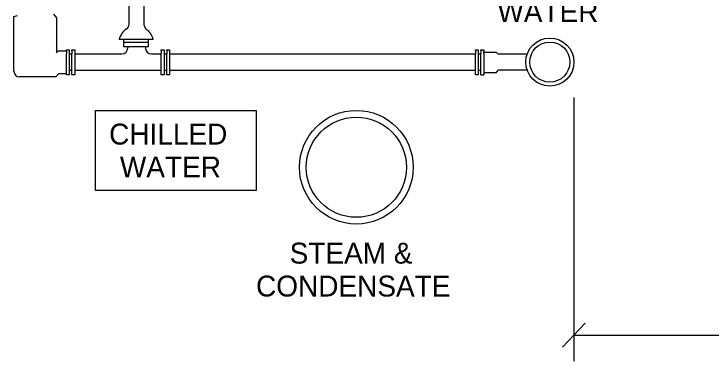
# Model space of a CAD drawing. Extents: x 27101070.6 to 27101150.6, y 1158854.7 to 1158902.9.
# Drawn here: x 27101080.64 to 27101098.02, y 1158875.06 to 1158883.73 of the extents above; entities that cross this region are included whole.
import ezdxf

# ---------------------------------------------------------------- set-up
doc = ezdxf.new("R2010")
doc.units = 0
for name, color, linetype in [('Default', 7, 'Continuous'), ('G-ANNO-TEXT', 7, 'Continuous'), ('G-DETL-LINE', 7, 'Continuous'), ('G-DETL-OTLN', 7, 'Continuous')]:
    doc.layers.add(name, color=color, linetype=linetype)

msp = doc.modelspace()

# ---------------------------------------------------------------- linework, layer by layer
at = {"layer": 'Default'}
for p, q in [((27101092.356, 1158882.728), (27101092.356, 1158882.797)), ((27101092.356, 1158882.318), (27101092.356, 1158882.249))]:
    msp.add_line(p, q, dxfattribs=at)
at = {"layer": 'G-ANNO-TEXT'}
for p, q in [((27101094.604, 1158881.636), (27101094.604, 1158875.058)), ((27101094.322, 1158875.407), (27101094.886, 1158876.008)), ((27101094.604, 1158875.707), (27101114.976, 1158875.707))]:
    msp.add_line(p, q, dxfattribs=at)
at = {"layer": 'G-DETL-LINE'}
for p, q in [((27101084.111, 1158883.088), (27101083.264, 1158883.088)), ((27101083.375, 1158883.088), (27101083.375, 1158882.908)), ((27101084, 1158882.908), (27101084, 1158883.088)), ((27101083.375, 1158883.019), (27101084, 1158883.019)), ((27101081.95, 1158882.831), (27101082.018, 1158882.831)), ((27101081.95, 1158882.805), (27101081.95, 1158882.831)), ((27101081.95, 1158882.805), (27101081.95, 1158882.728)), ((27101082.018, 1158882.831), (27101082.018, 1158882.206)), ((27101082.087, 1158882.831), (27101082.155, 1158882.831)), ((27101082.087, 1158882.805), (27101082.087, 1158882.831)), ((27101082.087, 1158882.805), (27101082.087, 1158882.728)), ((27101082.155, 1158882.831), (27101082.155, 1158882.206)), ((27101083.375, 1158882.908), (27101084, 1158882.908)), ((27101084.316, 1158882.831), (27101084.385, 1158882.831)), ((27101084.316, 1158882.805), (27101084.316, 1158882.831)), ((27101084.316, 1158882.805), (27101084.316, 1158882.728)), ((27101084.385, 1158882.831), (27101084.385, 1158882.206)), ((27101084.453, 1158882.831), (27101084.522, 1158882.831)), ((27101084.453, 1158882.805), (27101084.453, 1158882.831)), ((27101084.453, 1158882.805), (27101084.453, 1158882.728)), ((27101084.522, 1158882.831), (27101084.522, 1158882.206)), ((27101092.15, 1158882.805), (27101092.15, 1158882.831)), ((27101092.15, 1158882.831), (27101092.219, 1158882.831)), ((27101092.15, 1158882.805), (27101092.15, 1158882.728)), ((27101092.219, 1158882.831), (27101092.219, 1158882.206)), ((27101092.287, 1158882.831), (27101092.356, 1158882.831)), ((27101092.287, 1158882.805), (27101092.287, 1158882.831)), ((27101092.287, 1158882.805), (27101092.287, 1158882.728)), ((27101092.356, 1158882.831), (27101092.356, 1158882.206)), ((27101081.95, 1158882.206), (27101081.95, 1158882.728)), ((27101082.087, 1158882.206), (27101082.087, 1158882.728)), ((27101084.316, 1158882.206), (27101084.316, 1158882.728)), ((27101084.453, 1158882.206), (27101084.453, 1158882.728)), ((27101092.15, 1158882.206), (27101092.15, 1158882.728)), ((27101092.287, 1158882.206), (27101092.287, 1158882.728)), ((27101082.018, 1158882.206), (27101081.95, 1158882.206)), ((27101082.155, 1158882.206), (27101082.087, 1158882.206)), ((27101084.385, 1158882.206), (27101084.316, 1158882.206)), ((27101084.522, 1158882.206), (27101084.453, 1158882.206)), ((27101092.219, 1158882.206), (27101092.15, 1158882.206)), ((27101092.287, 1158882.206), (27101092.356, 1158882.206))]:
    msp.add_line(p, q, dxfattribs=at)
at = {"layer": 'G-DETL-OTLN'}
for p, q in [((27101083.512, 1158883.466), (27101083.512, 1158888.582)), ((27101083.889, 1158883.448), (27101083.889, 1158888.582)), ((27101080.641, 1158883.661), (27101080.726, 1158883.687)), ((27101080.641, 1158882.292), (27101080.641, 1158883.661)), ((27101081.625, 1158883.721), (27101081.702, 1158883.627)), ((27101081.702, 1158883.627), (27101081.702, 1158882.754)), ((27101081.702, 1158882.754), (27101081.745, 1158882.805)), ((27101081.745, 1158882.805), (27101081.95, 1158882.805)), ((27101083.48, 1158882.908), (27101083.48, 1158882.88)), ((27101083.921, 1158882.908), (27101083.921, 1158882.88)), ((27101092.356, 1158882.771), (27101092.664, 1158882.771)), ((27101092.664, 1158882.771), (27101092.707, 1158882.728)), ((27101082.018, 1158882.728), (27101082.087, 1158882.728)), ((27101082.155, 1158882.728), (27101083.328, 1158882.728)), ((27101084.073, 1158882.728), (27101084.316, 1158882.728)), ((27101084.385, 1158882.728), (27101084.453, 1158882.728)), ((27101084.522, 1158882.728), (27101092.15, 1158882.728)), ((27101092.219, 1158882.728), (27101092.287, 1158882.728)), ((27101092.707, 1158882.728), (27101093.44, 1158882.728)), ((27101081.753, 1158882.232), (27101081.685, 1158882.155)), ((27101081.95, 1158882.232), (27101081.753, 1158882.232)), ((27101082.018, 1158882.318), (27101082.087, 1158882.318)), ((27101082.155, 1158882.318), (27101084.316, 1158882.318)), ((27101084.385, 1158882.318), (27101084.453, 1158882.318)), ((27101084.522, 1158882.318), (27101092.15, 1158882.318)), ((27101092.219, 1158882.318), (27101092.287, 1158882.318)), ((27101092.664, 1158882.258), (27101092.356, 1158882.258)), ((27101092.664, 1158882.258), (27101092.715, 1158882.318)), ((27101093.44, 1158882.318), (27101092.715, 1158882.318)), ((27101081.685, 1158882.155), (27101080.778, 1158882.155)), ((27101082.677, 1158881.318), (27101086.677, 1158881.318)), ((27101082.677, 1158879.318), (27101082.677, 1158881.318)), ((27101086.677, 1158881.318), (27101086.677, 1158879.318)), ((27101086.677, 1158879.318), (27101082.677, 1158879.318))]:
    msp.add_line(p, q, dxfattribs=at)
for centre, radius in [((27101094.004, 1158882.523), 0.6), ((27101094.004, 1158882.523), 0.5), ((27101089.179, 1158879.898), 1.418), ((27101089.179, 1158879.898), 1.25)]:
    msp.add_circle(centre, radius, dxfattribs=at)
for centre, radius, start, end in [((27101083.375, 1158883.466), 0.137, 303.0679, 0), ((27101084.026, 1158883.448), 0.137, 180, 233.8089), ((27101083.688, 1158882.986), 0.435, 123.0679, 166.5554), ((27101083.688, 1158882.986), 0.435, 13.4446, 53.8089), ((27101083.328, 1158882.88), 0.152, 270, 0), ((27101084.073, 1158882.88), 0.152, 180, 270), ((27101080.778, 1158882.292), 0.137, 180, 270)]:
    msp.add_arc(centre, radius, start, end, dxfattribs=at)

# ---------------------------------------------------------------- texts
at = {"layer": 'G-ANNO-TEXT'}
for s, p in [('WATER', (27101092.696, 1158883.52)), ('CHILLED', (27101083.014, 1158880.464)), ('WATER', (27101083.283, 1158879.642)), ('STEAM &', (27101087.516, 1158877.492)), ('CONDENSATE', (27101086.678, 1158876.67))]:
    msp.add_text(s, height=0.522, dxfattribs=at).set_placement(p)

doc.saveas('drawing.dxf')
